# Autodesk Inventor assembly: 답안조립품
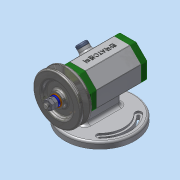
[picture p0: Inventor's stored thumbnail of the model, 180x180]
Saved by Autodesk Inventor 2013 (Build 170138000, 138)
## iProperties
Created: 2017-06
Part Number: 답안조립품
Document SubType Name: Assembly
Designer: dgall
Author: dgall
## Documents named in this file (14)
- C:\Users\dgall\Desktop\470607V1009\답안조립품.iam
- C:\Users\dgall\Desktop\470607V1009\V벨트풀리.ipt
- C:\Users\dgall\Desktop\470607V1009\베어링 15 x 32 x 9.ipt
- C:\Users\dgall\Desktop\470607V1009\본체.ipt
- C:\Users\dgall\Desktop\470607V1009\축.ipt
- C:\Users\dgall\Desktop\470607V1009\뒤커버.ipt
- C:\Users\dgall\Desktop\470607V1009\앞커버.ipt
- C:\Users\dgall\Desktop\470607V1009\볼트 M4 x 12.ipt
- C:\Users\dgall\Desktop\470607V1009\키 3 x 3 x 12.ipt
- C:\Users\dgall\Desktop\470607V1009\너트 M 8.ipt
- C:\Users\dgall\Desktop\470607V1009\스프링와셔 8.ipt
- C:\Users\dgall\Desktop\470607V1009\와셔 8x17.ipt
- C:\Users\dgall\Desktop\470607V1009\고무캡.ipt
- C:\Users\dgall\Desktop\470607V1009\오일 실 15 25 7.ipt
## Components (2 placed, 2 different names)
1. V벨트풀리:1 — 각도:2
2. 고무캡:1
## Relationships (1: Angle 1)
- 각도:2 [Angle]: V벨트풀리:1
